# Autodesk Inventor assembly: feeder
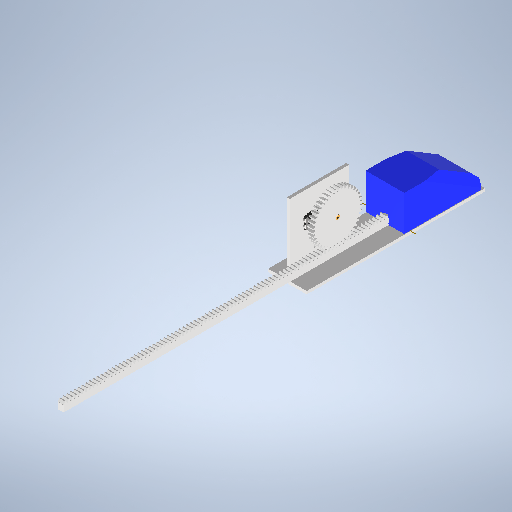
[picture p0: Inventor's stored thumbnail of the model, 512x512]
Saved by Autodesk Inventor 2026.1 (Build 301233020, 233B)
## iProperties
Created: 2026-10
Part Number: feeder
Document SubType Name: Assembly
Designer: alolo
Author: alolo
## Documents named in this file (9)
- C:\Users\hp\Documents\Inventor\DOM1_CartesianRobot\feeder.iam
- C:\Users\hp\Documents\Inventor\DOM1_CartesianRobot\pusher_pinion.ipt
- C:\Users\hp\Documents\Inventor\DOM1_CartesianRobot\Servo MG996R.ipt
- C:\Users\hp\Documents\Inventor\DOM1_CartesianRobot\pusher_base.ipt
- C:\Users\hp\Documents\Inventor\DOM1_CartesianRobot\pusher_support.ipt
- C:\Users\hp\Documents\Inventor\DOM1_CartesianRobot\pusher_punch.ipt
- C:\Users\hp\Documents\Inventor\DOM1_CartesianRobot\feeder_rack.ipt
- C:\Users\hp\Documents\Inventor\Content Center Files\R2026\en-US\ISO 4017(1)\ISO 4017 - M4 x 12 - ISO.ipt
- C:\Users\hp\Documents\Inventor\Content Center Files\R2026\en-US\ISO 4032(2)\ISO 4032 - M4 - ISO.ipt
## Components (14 placed, 8 different names)
1. Servo MG996R:1
2. pusher_base:1 — Mate:1, Mate:2, Mate:11, Mate:14, Mate:15, Slider:1
3. pusher_support
4. pusher_pinion:1 — Rotational:1, Flush:3, Rotation/Translation:1
5. pusher_punch:2 — Mate:14, Mate:16, Mate:17
6. feeder_rack:1 — Mate:15, Slider:1, Flush:3, Rotation/Translation:1, Mate:16, Mate:17
7. ISO 4017 M4 x 12:1 — Mate:18, Mate:19
8. ISO 4032 M4:1 — Mate:26, Mate:27
9. ISO 4017 M4 x 12:2 — Mate:20, Mate:21
10. ISO 4017 M4 x 12:3 — Mate:22, Mate:23
11. ISO 4017 M4 x 12:4 — Mate:24, Mate:25
12. ISO 4032 M4:2 — Mate:28, Mate:29
13. ISO 4032 M4:3 — Mate:30, Mate:31
14. ISO 4032 M4:4 — Mate:32, Mate:33
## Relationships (27: Mate 23, RevoluteJoint 1, TranslationJoint 1, Flush 1, RelateRotateTranslate 1)
- Mate:1: pusher_base:1
- Mate:2: pusher_base:1
- Rotational:1 [RevoluteJoint]: pusher_pinion:1
- Mate:11: pusher_base:1
- Mate:14: pusher_base:1 ↔ pusher_punch:2
- Mate:15: pusher_base:1 ↔ feeder_rack:1
- Slider:1 [TranslationJoint]: pusher_base:1 ↔ feeder_rack:1
- Flush:3: pusher_pinion:1 ↔ feeder_rack:1
- Rotation/Translation:1 [RelateRotateTranslate]: pusher_pinion:1 ↔ feeder_rack:1
- Mate:16: pusher_punch:2 ↔ feeder_rack:1
- Mate:17: pusher_punch:2 ↔ feeder_rack:1
- Mate:18: ISO 4017 M4 x 12:1
- Mate:19: ISO 4017 M4 x 12:1
- Mate:20: ISO 4017 M4 x 12:2
- Mate:21: ISO 4017 M4 x 12:2
- Mate:22: ISO 4017 M4 x 12:3
- Mate:23: ISO 4017 M4 x 12:3
- Mate:24: ISO 4017 M4 x 12:4
- Mate:25: ISO 4017 M4 x 12:4
- Mate:26: ISO 4032 M4:1
- Mate:27: ISO 4032 M4:1
- Mate:28: ISO 4032 M4:2
- Mate:29: ISO 4032 M4:2
- Mate:30: ISO 4032 M4:3
- Mate:31: ISO 4032 M4:3
- Mate:32: ISO 4032 M4:4
- Mate:33: ISO 4032 M4:4
